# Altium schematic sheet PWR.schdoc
size 1117 x 863 mm; Symbol: Drawing-Symbol_A4; Company: 嘉立创EDA; Version: V1.0; Page Size: A4; @Project Name: OpenECG; @Update Date: 2026-05-05; @Create Date: 2026-05-05; Device: Drawing-Symbol_A4; @Board Name: #第七届立创电赛#卡片型多参数监护仪-OpenECG; @Page Name: P1; @Create Time: 15:25:49; @Page Count: 8; @Page No: 8; @Schematic Name: #第七届立创电赛#卡片型多参数监护仪-OpenECG; @Update Time: 15:25:49; @Assembly Variant: Basic; Border: 1; Title Block Position: 3; Size: A4; Width: 4400; Height: 3400; Region Start: 1; X Region Count: 6; Y Region Count: 4; Blade Width: 10
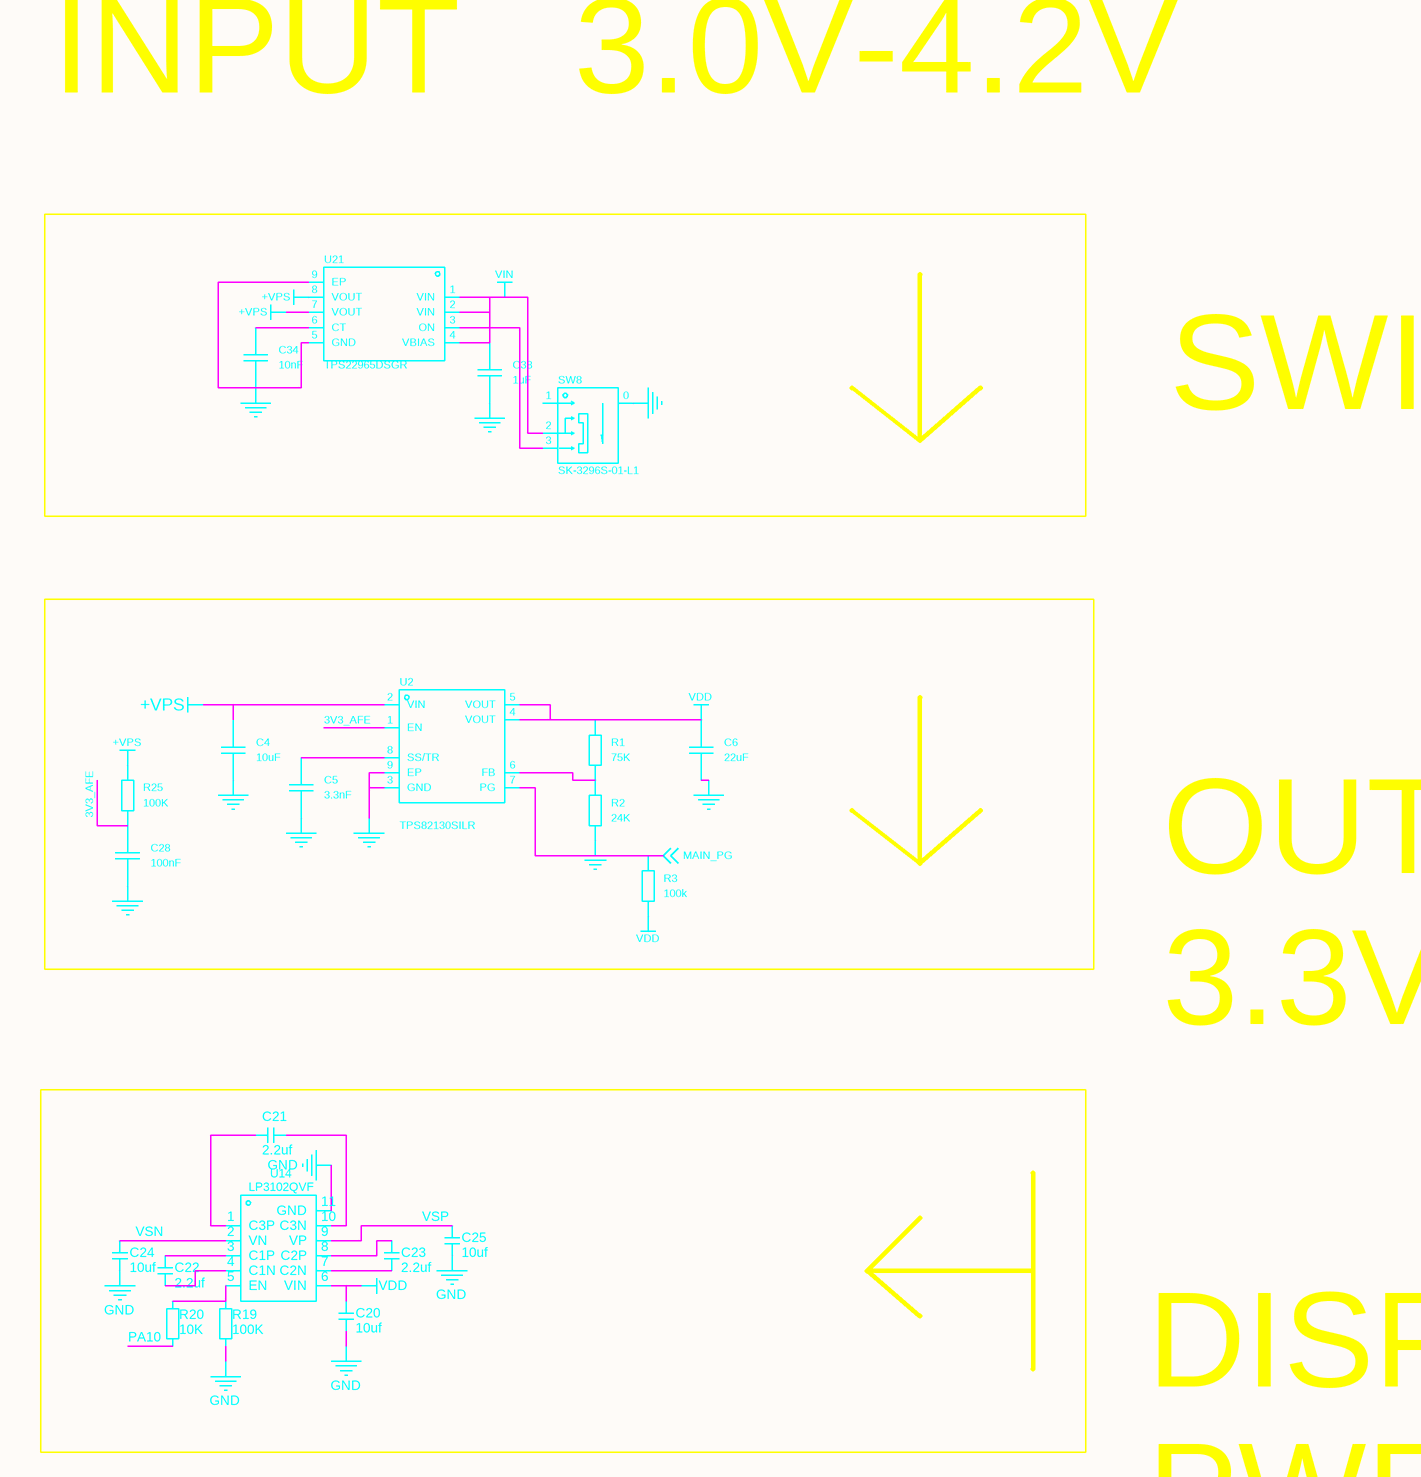
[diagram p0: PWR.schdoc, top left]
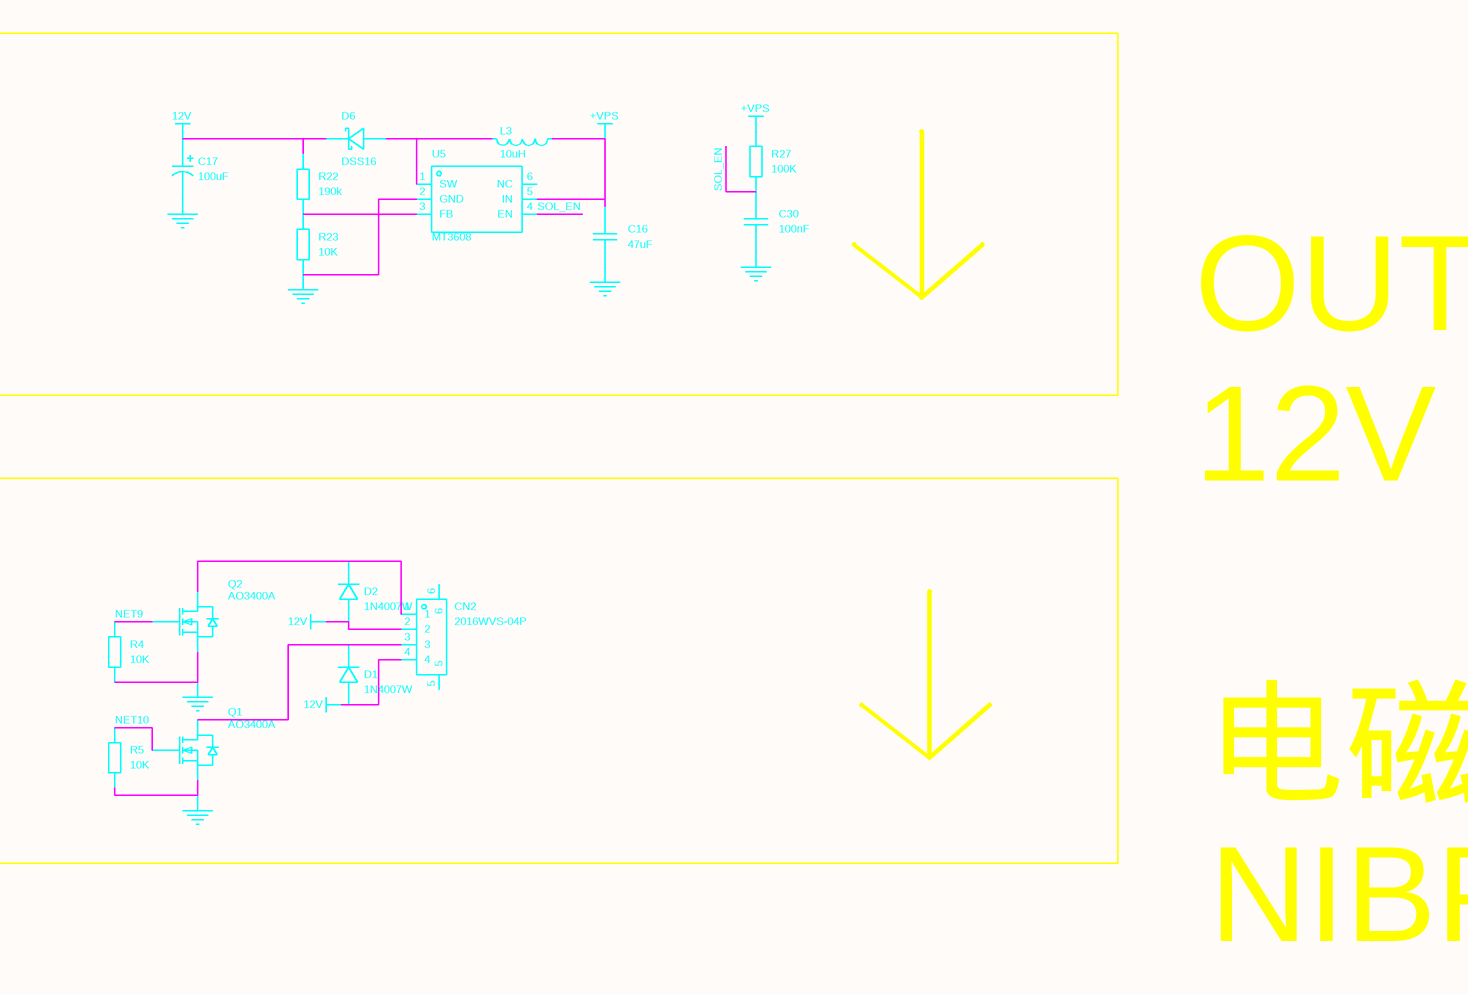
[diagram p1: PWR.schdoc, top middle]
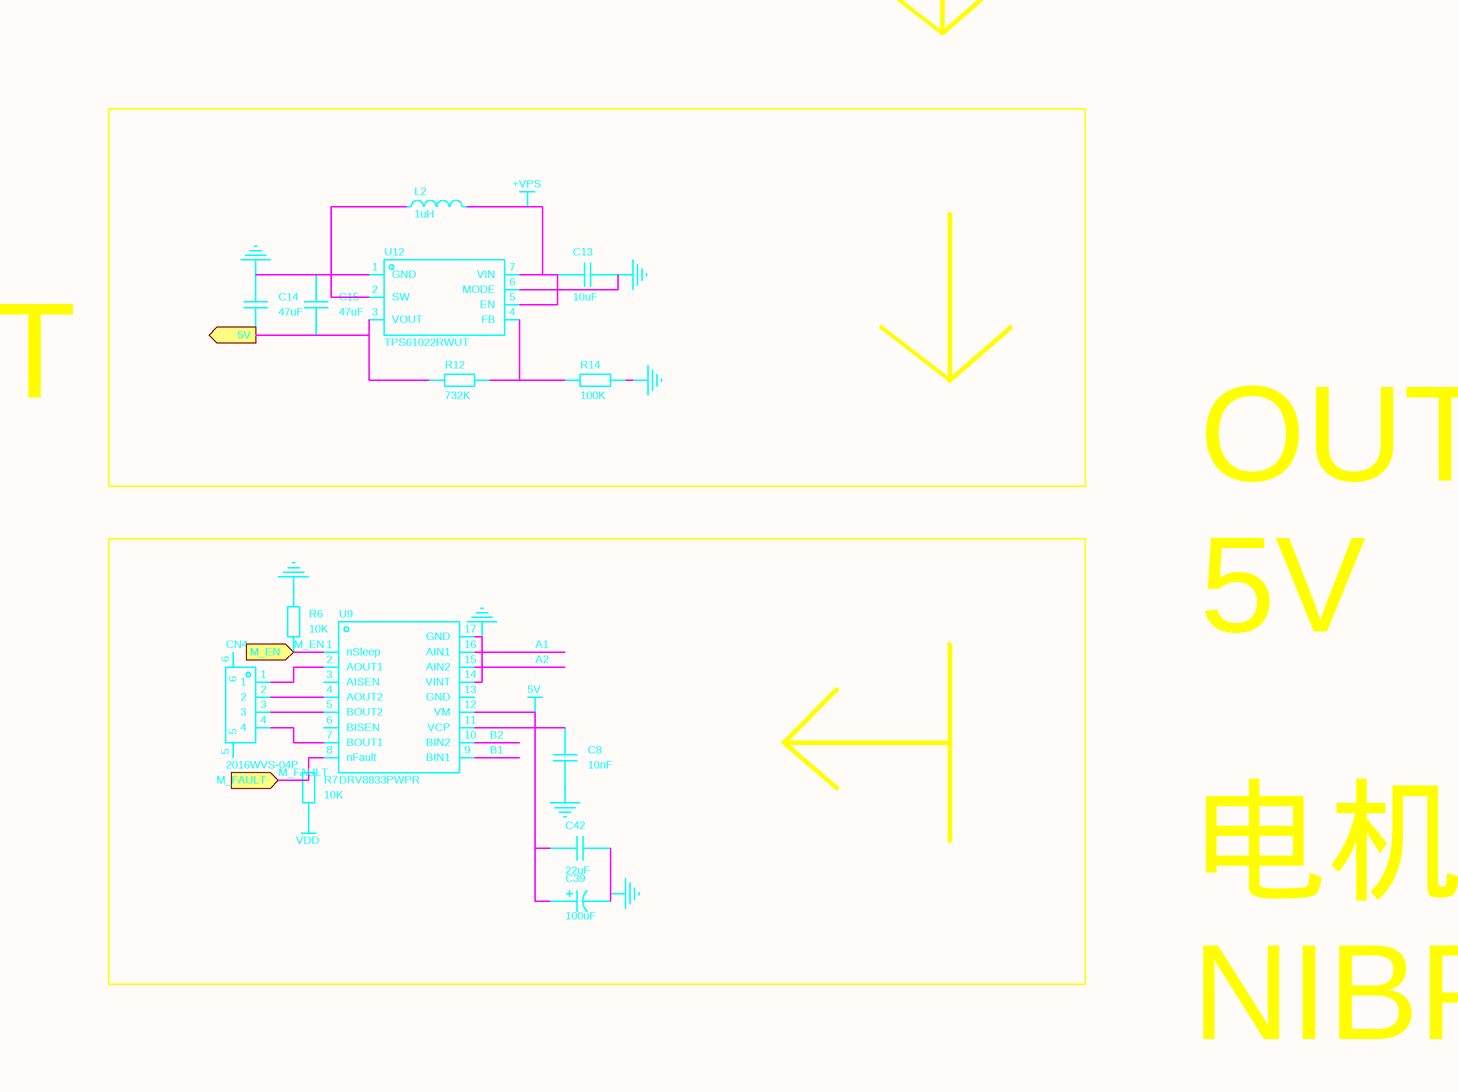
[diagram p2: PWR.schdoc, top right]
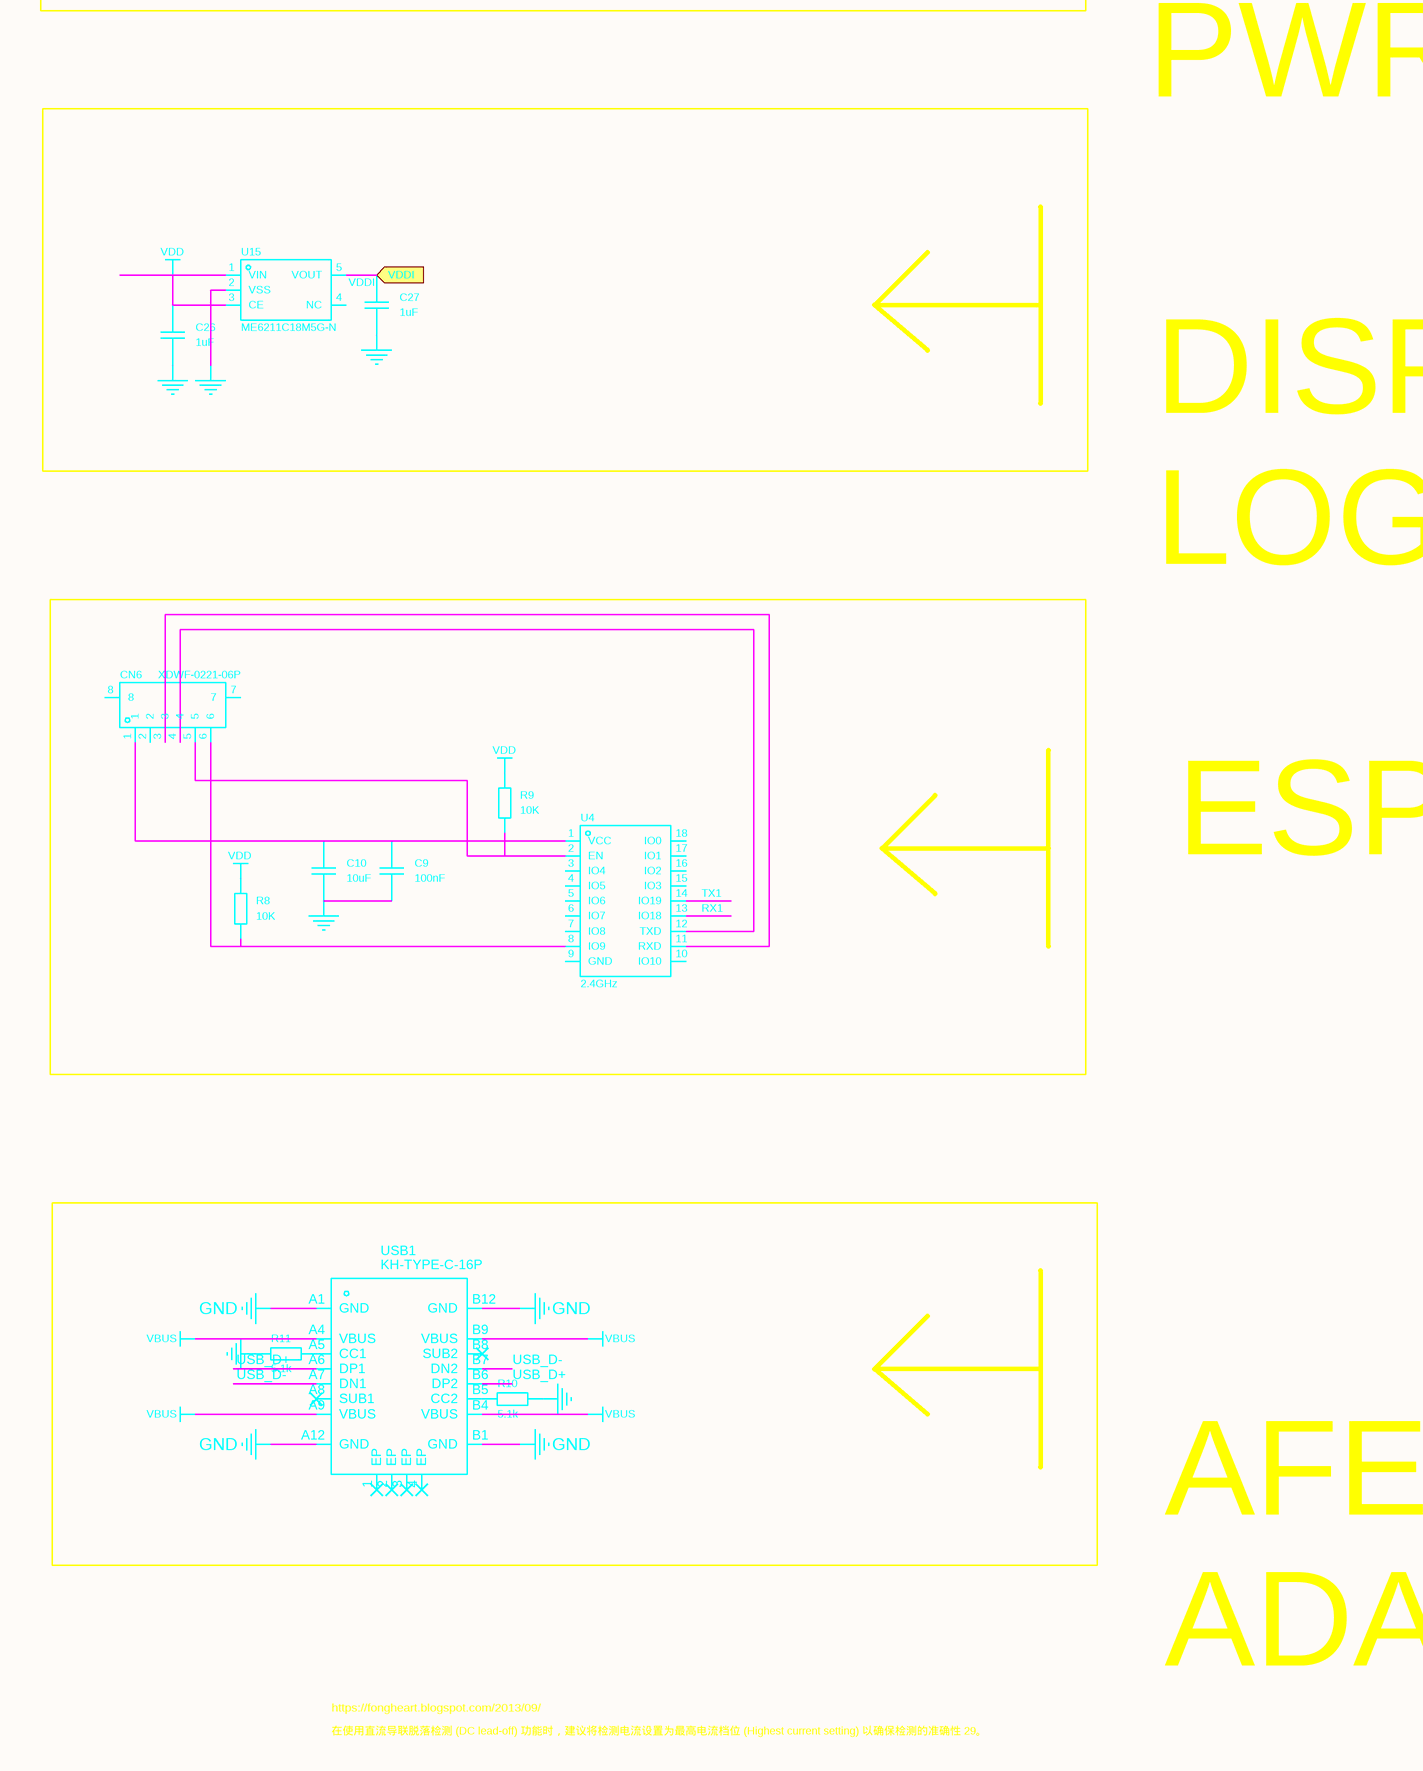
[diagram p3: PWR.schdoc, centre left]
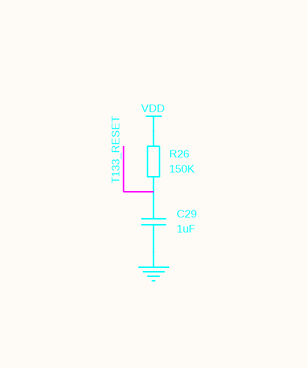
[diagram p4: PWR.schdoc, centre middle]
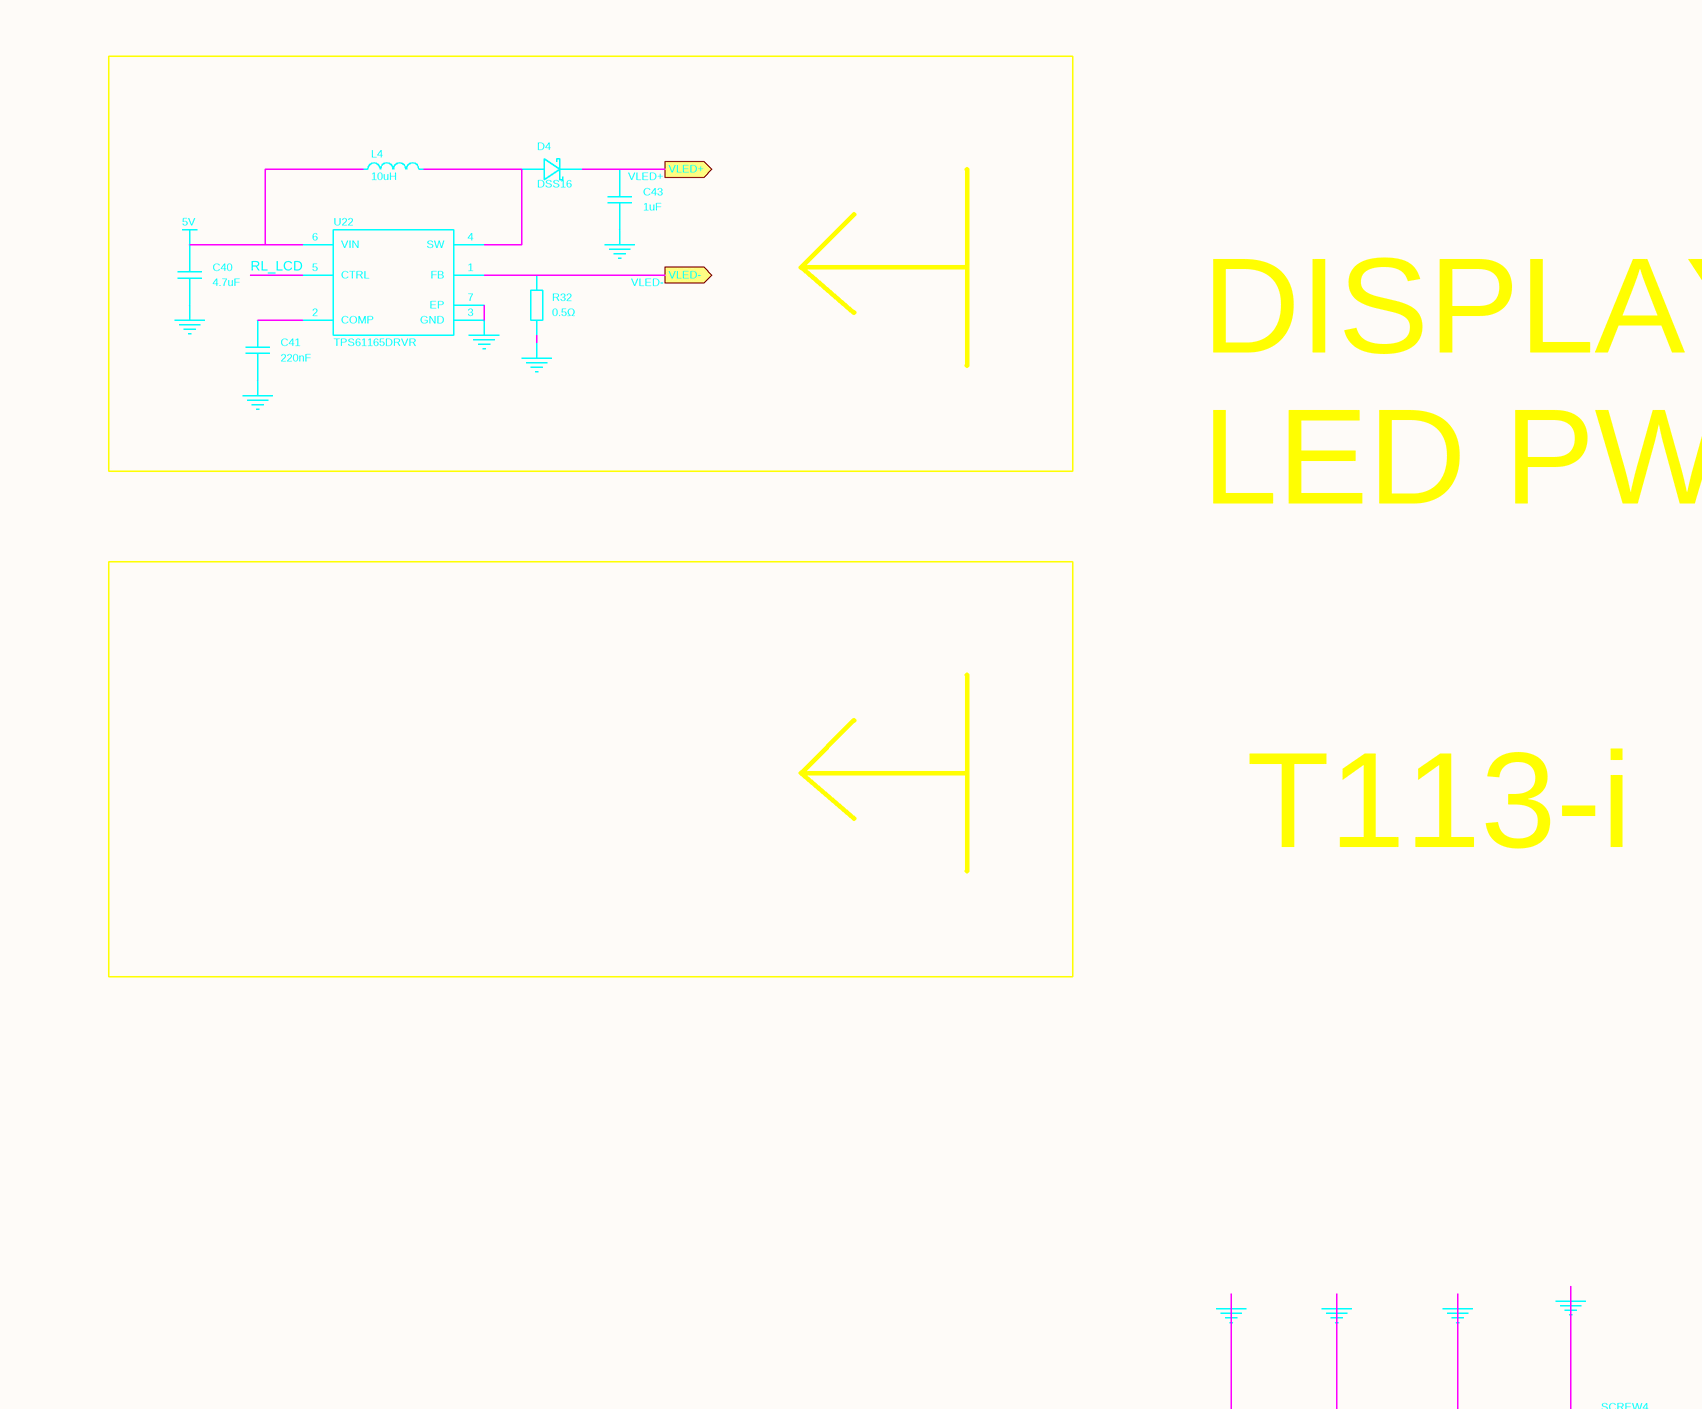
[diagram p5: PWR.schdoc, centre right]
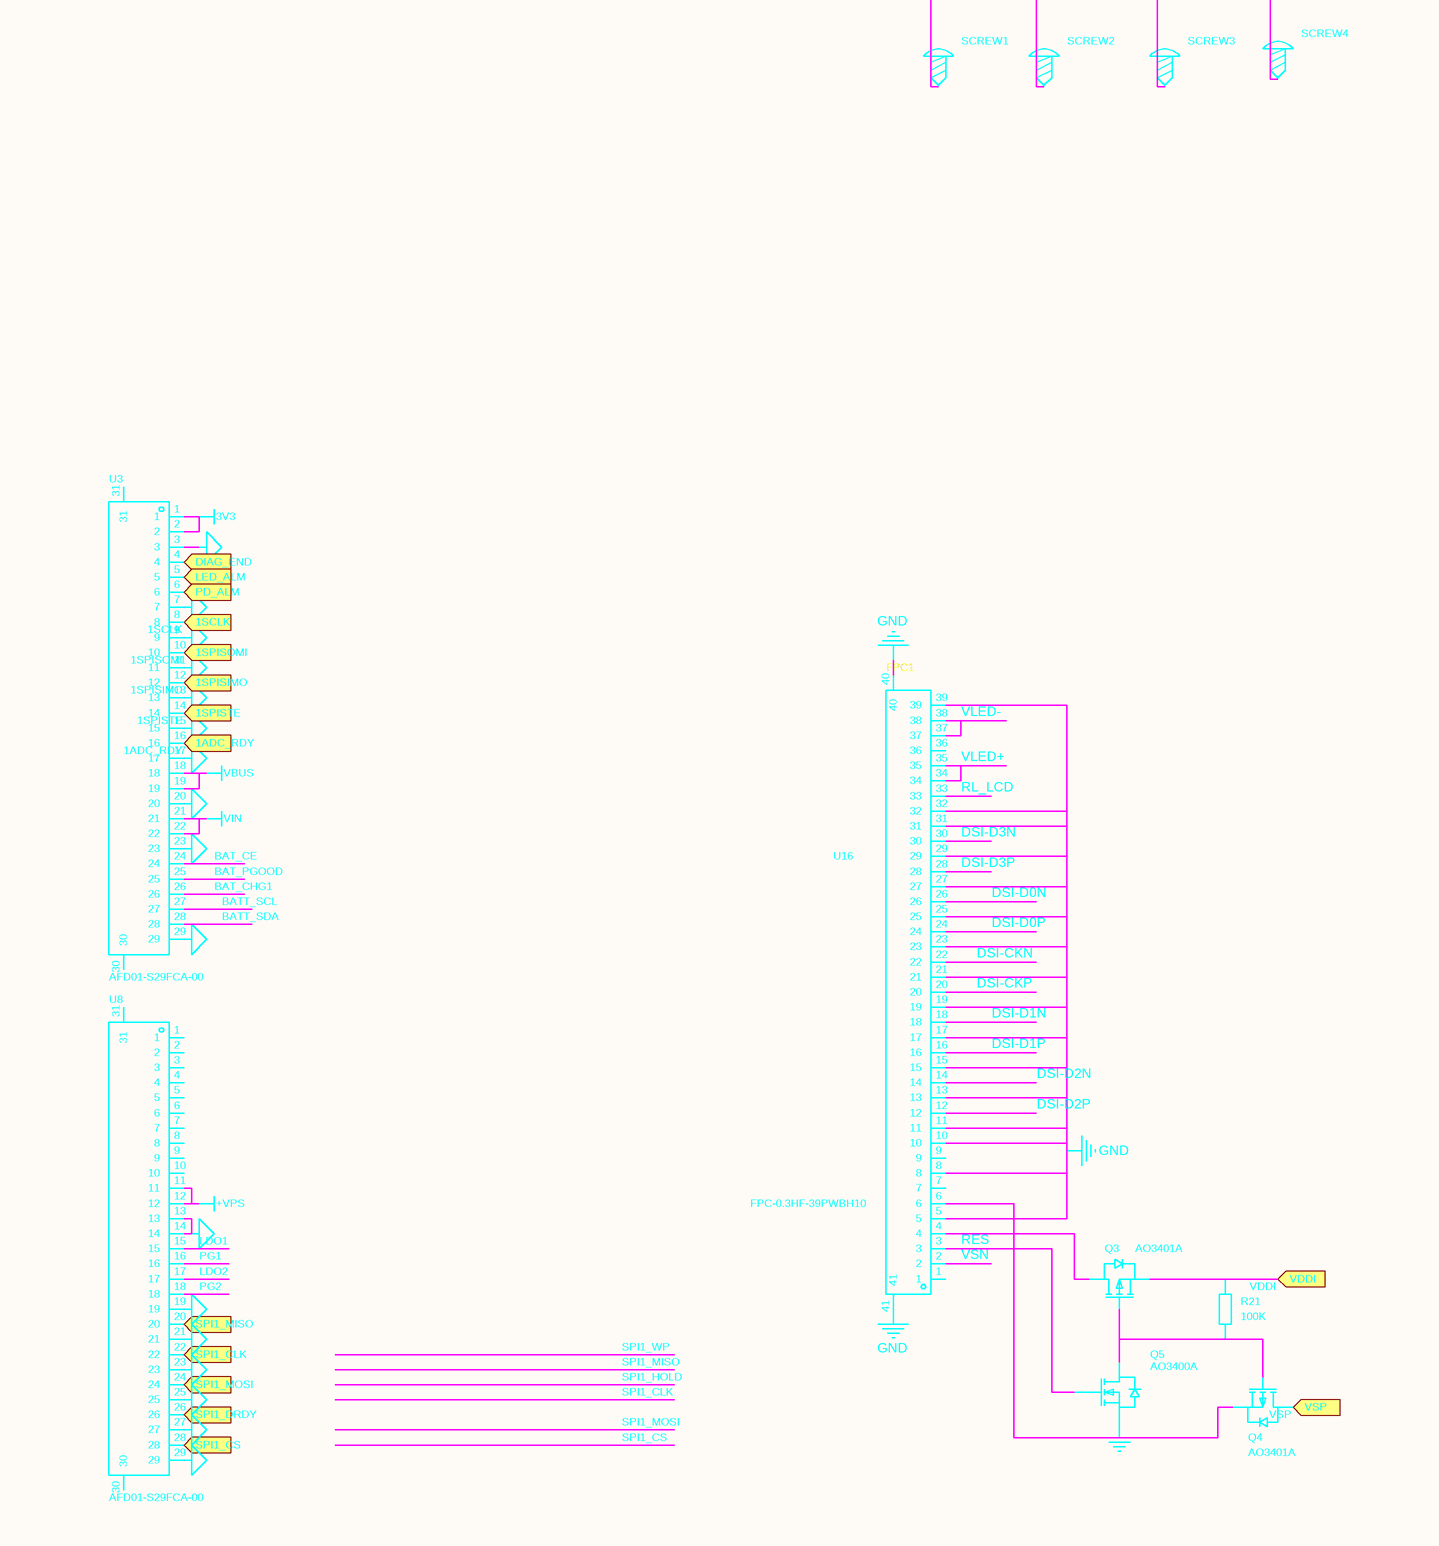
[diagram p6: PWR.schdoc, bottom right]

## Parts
C4  10uF  [C0805]
C5  3.3nF  [C0603]
C6  22uF  [C0805]
C8  10nF  [C0603]
C9  100nF  [C0603]
C10  10uF  [C0603]
C13  10uF  [C0603]
C14  47uF  [C0603]
C15  47uF  [C0603]
C16  47uF  [C0805]
C17  100uF  [CAP-SMD_BD5.0-L5.3-W5.3-LS6.0-FD-H5.7]
C20  10uf  [C0603]
C21  2.2uf  [R0603]
C22  2.2uf  [R0603]
C23  2.2uf  [R0603]
C24  10uf  [C0603]
C25  10uf  [C0603]
C26  1uF  [C0603]
C27  1uF  [C0603]
C28  100nF  [C0603]
C29  1uF  [C0603]
C30  100nF  [C0603]
C34  10nF  [C0603]
C38  1uF  [C0603]
C39  100uF  [CAP-SMD_BD5.0-L5.3-W5.3-LS6.0-FD-H5.7]
C40  4.7uF  [C0603]
C41  220nF  [C0603]
C42  22uF  [C0805]
C43  1uF  [C0603]
CN2  2016WVS-04P  [CONN-SMD_2016WVS-04P]
CN4  2016WVS-04P  [CONN-SMD_2016WVS-04P]
CN6  XDWF-0221-06P  [CONN-SMD_XDWF-0221-06P]
D1  1N4007W  [SOD-123FL_L2.7-W1.8-LS3.8-RD]
D2  1N4007W  [SOD-123FL_L2.7-W1.8-LS3.8-RD]
D4  DSS16  [SOD-123FL_L2.8-W1.8-LS3.7-R-RD]
D6  DSS16  [SOD-123FL_L2.8-W1.8-LS3.7-R-RD]
L2  1uH  [IND-SMD_L4.4-W4.2]
L3  10uH  [IND-SMD_L2.5-W2.0-VLS252012CX-150M]
L4  10uH  [IND-SMD_L2.5-W2.0_FHD252012S-6R8MT]
Q1  AO3400A  [SOT-23-3_L2.9-W1.3-P1.90-LS2.4-BR]
Q2  AO3400A  [SOT-23-3_L2.9-W1.3-P1.90-LS2.4-BR]
Q3  AO3401A  [SOT-23_L2.9-W1.3-P1.90-LS2.4-BR]
Q4  AO3401A  [SOT-23_L2.9-W1.3-P1.90-LS2.4-BR]
Q5  AO3400A  [SOT-23-3_L2.9-W1.3-P1.90-LS2.4-BR]
R1  75K  [R0603]
R2  24K  [R0603]
R3  100k  [R0603]
R4  10K  [R0603]
R5  10K  [R0603]
R6  10K  [R0603]
R7  10K  [R0603]
R8  10K  [R0603]
R9  10K  [R0603]
R10  5.1k  [R0603]
R11  5.1k  [R0603]
R12  732K  [R0603]
R14  100K  [R0603]
R19  100K  [R0603]
R20  10K  [R0603]
R21  100K  [R0603]
R22  190k  [R0603]
R23  10K  [R0603]
R25  100K  [R0603]
R26  150K  [R0603]
R27  100K  [R0603]
R32  0.5Ω  [R0603]
SCREW1  (no value)  [M3螺丝]
SCREW2  (no value)  [M3螺丝]
SCREW3  (no value)  [M3螺丝]
SCREW4  (no value)  [M3螺丝]
SW8  SK-3296S-01-L1  [SW-SMD_3P-P1.50_L2.7-W6.6]
U2  TPS82130SILR  [USIP-8_L3.0-W2.8-P0.65-TL-EP]
U3  AFD01-S29FCA-00  [FPC-SMD_29P-P0.50_JS_AFD01-S29FCA-00]
U4  2.4GHz  [WIFI-SMD_L20.0-W18.0_ESP32-C3-WROOM-02U-N4]
U5  MT3608  [SOT-23-6_L2.9-W1.6-P0.95-LS2.8-BL]
U8  AFD01-S29FCA-00  [FPC-SMD_29P-P0.50_JS_AFD01-S29FCA-00]
U9  DRV8833PWPR  [TSSOP-16_L5.0-W4.4-P0.65-LS6.4-BL-EP]
U12  TPS61022RWUT  [VQFN-7_L2.0-W2.0-P0.55-TL_RWU]
U14  LP3102QVF  [TDFN-10_L3.0-W3.0-P0.50-BL-EP]
U15  ME6211C18M5G-N  [SOT-23-5_L3.0-W1.7-P0.95-LS2.8-BR]
U16  FPC-0.3HF-39PWBH10  [LQ055T3SX02Z]
U21  TPS22965DSGR  [UDFN-8_L2.0-W2.0-P0.50-TL-EP]
U22  TPS61165DRVR  [WSON-6_L2.0-W2.0-P0.65-TL-EP]
USB1  KH-TYPE-C-16P  [USB-C-SMD_KH-TYPE-C-16P]

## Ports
1ADC_RDY (in), 1SCLK (in), 1SPISIMO (in), 1SPISOMI (in), 1SPISTE (in), 5V (out), DIAG_END (in), LED_ALM (in), M_EN (in), M_FAULT (in), PD_ALM (in), SPI1_CLK (in), SPI1_CS (in), SPI1_DRDY (in), SPI1_MISO (in), SPI1_MOSI (in), VDDI (in), VLED+ (out), VLED- (out), VSP (in)

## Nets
3V3: U3.1 U3.2
5V: C39.1 C40.2 C42.2 L4.1 U9.12(VM) U22.6(VIN)
12V: C17.1 CN2.2 CN2.4 D1.2(A) D2.2(A) D6.2(K) R22.2
+VPS: C4.1 C13.1 C16.2 L2.2 L3.1 R25.2 R27.2 U2.2(VIN) U5.5(IN) U8.11 U8.12 U12.5(EN) U12.7(VIN) U21.7(VOUT) U21.8(VOUT)
AGND: U3.3 U3.7 U3.9 U3.11 U3.13 U3.15 U3.17 U3.20 U3.23 U3.29 U8.13 U8.14 U8.19 U8.21 U8.23 U8.25 U8.27 U8.29
GND: C4.2 C5.1 C6.1 C8.1 C9.1 C10.1 C13.2 C14.2 C15.2 C16.1 C17.2 C20.1 C24.1 C25.1 C26.1 C27.1 C28.1 C29.1 C30.1 C34.1 C38.1 C39.2 C40.1 C41.1 C42.1 C43.1 Q1.2(S) Q2.2(S) Q5.2(S) R2.1 R4.1 R5.1 R6.2 R10.2 R11.1 R14.2 R19.2 R23.1 R32.1 SCREW1.1 SCREW2.1 SCREW3.1 SCREW4.1 SW8.0 U2.3(GND) U2.9(EP) U5.2(GND) U9.14(VINT) U9.17(GND) U12.1(GND) U12.6(MODE) U14.11(GND) U15.2(VSS) U16.5 U16.8 U16.10 U16.11 U16.13 U16.15 U16.17 U16.19 U16.21 U16.23 U16.25 U16.27 U16.29 U16.31 U16.32 U16.39 U16.40 U16.41 U21.5(GND) U21.9(EP) U22.3(GND) U22.7(EP) USB1.A1(GND) USB1.A12(GND) USB1.B1(GND) USB1.B12(GND)
VBUS: U3.18 U3.19 USB1.A4(VBUS) USB1.A9(VBUS) USB1.B4(VBUS) USB1.B9(VBUS)
VDD: C6.2 C20.2 C26.2 R1.2 R3.1 R7.1 R8.2 R9.2 R26.2 U2.4(VOUT) U2.5(VOUT) U14.6(VIN) U15.1(VIN) U15.3(CE)
VIN: C38.2 SW8.2 U3.21 U3.22 U21.1(VIN) U21.2(VIN) U21.4(VBIAS)
1ADC_RDY: U3.16 ; port 1ADC_RDY
1SCLK: U3.8 ; port 1SCLK
1SPISIMO: U3.12 ; port 1SPISIMO
1SPISOMI: U3.10 ; port 1SPISOMI
1SPISTE: U3.14 ; port 1SPISTE
3V3_AFE: C28.2 R25.1 U2.1(EN)
5V: C14.1 C15.1 R12.1 U12.3(VOUT) ; port 5V  [a separate net that carries the same name]
A1: U9.16(AIN1)
A2: U9.15(AIN2)
B1: U9.9(BIN1)
B2: U9.10(BIN2)
BAT_CE: U3.24
BAT_CHG1: U3.26
BAT_PGOOD: U3.25
BATT_SCL: U3.27
BATT_SDA: U3.28
DIAG_END: U3.4 ; port DIAG_END
DSI-CKN: U16.22
DSI-CKP: U16.20
DSI-D0N: U16.26
DSI-D0P: U16.24
DSI-D1N: U16.18
DSI-D1P: U16.16
DSI-D2N: U16.14
DSI-D2P: U16.12
DSI-D3N: U16.30
DSI-D3P: U16.28
LDO1: U8.15
LDO2: U8.17
LED_ALM: U3.5 ; port LED_ALM
M_EN: R6.1 U9.1(nSleep) ; port M_EN
M_FAULT: R7.2 U9.8(nFault) ; port M_FAULT
MAIN_PG: R3.2 U2.7(PG) ; off-sheet MAIN_PG
NET9: Q2.1(G) R4.2
NET10: Q1.1(G) R5.2
PA10: R20.2
PD_ALM: U3.6 ; port PD_ALM
PG1: U8.16
PG2: U8.18
RES: Q5.1(G) U16.3
RL_LCD: U16.33 U22.5(CTRL)
RX1: U4.13(IO18)
SOL_EN: C30.2 R27.1 U5.4(EN)
SPI1_CLK: U8.22 ; port SPI1_CLK
SPI1_CS: U8.28 ; port SPI1_CS
SPI1_DRDY: U8.26 ; port SPI1_DRDY
SPI1_MISO: U8.20 ; port SPI1_MISO
SPI1_MOSI: U8.24 ; port SPI1_MOSI
T133_RESET: C29.2 R26.1
TX1: U4.14(IO19)
USB_D+: USB1.A6(DP1) USB1.B6(DP2)
USB_D-: USB1.A7(DN1) USB1.B7(DN2)
VDDI: C27.2 Q3.2(S) R21.2 U15.5(VOUT) ; port VDDI
VLED+: C43.2 D4.2(K) U16.34 U16.35 ; port VLED+
VLED-: R32.2 U16.37 U16.38 U22.1(FB) ; port VLED-
VSN: C24.2 U14.2(VN) U16.2
VSP: C25.2 Q4.3(D) U14.9(VP) ; port VSP
NetC5_2: C5.2 U2.8(SS/TR)
NetC8_2: C8.2 U9.11(VCP)
NetC9_2: C9.2 C10.2 CN6.1 U4.1(VCC)
NetC21_1: C21.1 U14.10(C3N)
NetC21_2: C21.2 U14.1(C3P)
NetC22_1: C22.1 U14.3(C1P)
NetC22_2: C22.2 U14.4(C1N)
NetC23_1: C23.1 U14.8(C2P)
NetC23_2: C23.2 U14.7(C2N)
NetC34_2: C34.2 U21.6(CT)
NetC41_2: C41.2 U22.2(COMP)
NetCN2_1: CN2.1 D2.1(K) Q2.3(D)
NetCN2_3: CN2.3 D1.1(K) Q1.3(D)
NetCN4_1: CN4.1 U9.2(AOUT1)
NetCN4_2: CN4.2 U9.4(AOUT2)
NetCN4_3: CN4.3 U9.5(BOUT2)
NetCN4_4: CN4.4 U9.7(BOUT1)
NetCN6_3: CN6.3 U4.11(RXD)
NetCN6_4: CN6.4 U4.12(TXD)
NetCN6_5: CN6.5 R9.1 U4.2(EN)
NetCN6_6: CN6.6 R8.1 U4.8(IO9)
NetD4_1: D4.1(A) L4.2 U22.4(SW)
NetD6_1: D6.1(A) L3.2 U5.1(SW)
NetL2_1: L2.1 U12.2(SW)
NetQ3_1: Q3.1(G) Q4.1(G) Q5.3(D) R21.1
NetQ3_3: Q3.3(D) U16.4
NetQ4_2: Q4.2(S) U16.6
NetR1_1: R1.1 R2.2 U2.6(FB)
NetR10_1: R10.1 USB1.B5(CC2)
NetR11_2: R11.2 USB1.A5(CC1)
NetR12_2: R12.2 R14.1 U12.4(FB)
NetR19_1: R19.1 R20.1 U14.5(EN)
NetR22_1: R22.1 R23.2 U5.3(FB)
NetSW8_3: SW8.3 U21.3(ON)

Not connected (* = marked no-connect by the designer): CN2 5 6; CN4 5 6; CN6 2 7 8; SW8 1; U3 30 31; U4 3(IO4) 4(IO5) 5(IO6) 6(IO7) 7(IO8) 9(GND) 10(IO10) 15(IO3) 16(IO2) 17(IO1) 18(IO0); U5 6(NC); U8 1 2 3 4 5 6 7 8 9 10 30 31; U9 3(AISEN) 6(BISEN) 13(GND); U15 4(NC); U16 1 7 9 36; USB1 1(EP)* 2(EP)* 3(EP)* 4(EP)* A8(SUB1)* B8(SUB2)*

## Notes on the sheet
- INPUT   3.0V-4.2V
- SWITCH
- OUTPUT
  3.3V
- OUTPUT
  12V
- OUTPUT
  5V
- DISPLAY
  PWR
- 电磁阀
  NIBP
- 电机
  NIBP
- DISPLAY
  LOGIC PWR
- DISPLAY
  LED PWR
- ESP32-C3
- T113-i
- AFE4400
  ADAS1000
- https://fongheart.blogspot.com/2013/09/
- 在使用直流导联脱落检测 (DC lead-off) 功能时，建议将检测电流设置为最高电流档位 (Highest current setting) 以确保检测的准确性 29。

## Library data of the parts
C4-C6 C8-C10 C13-C16 C26-C30 C34 C38 C40 C41 C43 = CAP_0603: Symbol: Capacitance; 3D Model: ac125912035d415993ca9572d50418b1; 3D Model Transform: 62.992,31.496,0,0,0,0,0,0,0; ConvertToPcb: yes; ModelName: C0603_L1.6-W0.8-H0.8
C17 = JVJ10V100M5x5: 容值:100uF;精度:±20%;额定电压:10V;纹波电流:45mA@120Hz;; Manufacturer: JIERR(捷而瑞); 3D Model: 55d82bd915ff4bdcad2abd5b7fba61690819f05c4eef4c71ace90d822a990e87; 3D Model Transform: 236.22,208.661,0,0,0,0,0,0,0; Tolerance: ±20%; Voltage Rating: 10V; Lifetime: 2000hrs@105℃; AddInBom: yes
C20-C25 = 电容-0402: Capacitor; Value: 0.1u; Origin Footprint: CAP_0402; Origin 3D Model Title: User Library-0603 SMD Capacitor; AddInBom: yes
C39 = JVJ10V100M5x5: 容值:100uF;精度:±20%;额定电压:10V;纹波电流:45mA@120Hz;; Manufacturer: JIERR(捷而瑞); AddInBom: yes; ModelId: 55d82bd915ff4bdcad2abd5b7fba61690819f05c4eef4c71ace90d822a990e87; ModelTransform: 236.22,208.661,0,0,0,0,0,0,0; Tolerance: ±20%; Voltage Rating: 10V; Lifetime: 2000hrs@105℃
C42 = C2012X5R1V226MT000E: 容值:22uF;精度:±20%;额定电压:35V;温度系数:X5R;; Manufacturer: TDK; AddInBom: yes; ModelId: 1ba041120af144c991958decab20d2410819f05c4eef4c71ace90d822a990e87; ModelName: C0805_L2.0-W1.3-H1.3; ModelTransform: 78.74,51.181,0,0,0,0,0,0.0005,0; Tolerance: ±20%; Voltage Rating: 35V; Temperature Coefficient: X5R
CN2 CN4 = 2016WVS-04P: 插针结构:1x4P;间距:2mm;安装方式:立贴;参考系列:PH;总PIN数:4P;排数:1;每排PIN数:4;触头材质:黄铜;触头镀层:锡;; Manufacturer: HanElectricity(瀚源); Pins Structure: 1x4P; Pitch: 2mm; Reference Series: PH; Number of PINs Per Row: 4; Plastic Material: LCP; Flame Retardant Rating: UL94V-0; Z-Height of the Board: 6.2mm; Y-Width of Bottom Edge on Board: 5.4mm; AddInBom: yes
CN6 = XDWF-0221-06P: 插针结构:1x6P;间距:2mm;安装方式:立贴;总PIN数:6P;排数:1;每排PIN数:6;额定电流:3A;触头材质:铜;触头镀层:锡;工作温度:-40℃~+85℃;; Manufacturer: LX(连欣科技); AddInBom: yes; ModelId: 3330ab840f6a417aaed60c53b1a588890819f05c4eef4c71ace90d822a990e87; ModelTransform: 627.952,293.3065,0,0,0,0,0,-40.905,0; Pins Structure: 1x6P; Pitch: 2mm; Number of PINs Per Row: 6; Current Rating: 3A; Voltage Rating: 100V; Plastic Material: LCP; Z-Height of the Board: 7.4mm; Y-Width of Bottom Edge on Board: 7.45mm
D1 D2 = 1N4007W_C18199088: 二极管配置:独立式;正向压降(Vf):1V@1A;直流反向耐压(Vr):1kV;整流电流:1A;; Manufacturer: R+O(宏嘉诚); 3D Model: 86f9151e155e4fe2af0c4f2e0a80302e0819f05c4eef4c71ace90d822a990e87; 3D Model Transform: 141.732,70.866,0,180,0,0,0,0,0; Diode Configuration: 独立式; Voltage - Forward(Vf@If): 1V@1A; Voltage - DC Reverse(Vr): 1kV; Current - Rectified: 1A; Reverse Leakage Current (Ir): 2uA@1000V; Non-Repetitive Peak Forward Surge Current: 30A; Operating Junction Temperature Range: -55℃~+150℃; AddInBom: yes; ModelName: SOD-123FL_L2.8-W1.8-H1.1-LS3.6
D4 = DSS16_C2923924: 二极管配置:独立式;正向压降(Vf):700mV@1A;直流反向耐压(Vr):60V;整流电流:1A;; Manufacturer: CJ(江苏长电/长晶); AddInBom: yes; ModelId: 8393683a03e6444f97e03ed1558f3a520819f05c4eef4c71ace90d822a990e87; ModelTransform: 143.701,70.3249,0,0,0,0,0,0,0; Diode Configuration: 独立式; Voltage - DC Reverse(Vr): 60V; Current - Rectified: 1A; Reverse Leakage Current (Ir): 500uA@60V; Operating Junction Temperature Range: -55℃~+150℃; Non-Repetitive Peak Forward Surge Current: 30A
D6 = DSS16_C2923924: 二极管配置:独立式;正向压降(Vf):700mV@1A;直流反向耐压(Vr):60V;整流电流:1A;; Manufacturer: CJ(江苏长电/长晶); 3D Model: 8393683a03e6444f97e03ed1558f3a520819f05c4eef4c71ace90d822a990e87; 3D Model Transform: 143.701,70.3249,0,0,0,0,0,0,0; Diode Configuration: 独立式; Voltage - DC Reverse(Vr): 60V; Current - Rectified: 1A; Reverse Leakage Current (Ir): 500uA@60V; Operating Junction Temperature Range: -55℃~+150℃; Non-Repetitive Peak Forward Surge Current: 30A; AddInBom: yes
L2 = FXL0420-1R0-M: 电感值:1uH;精度:±20%;额定电流:6A;饱和电流(Isat):7A;类型:一体成型电感;; Manufacturer: cjiang(长江微电); AddInBom: yes; ModelId: e9b3d3f4fa134185b54d517730715f160819f05c4eef4c71ace90d822a990e87; ModelName: IND-SMD_L4.2-W4.4-H2.0; ModelTransform: 173.228,165.354,0,0,0,0,0,0,0; Tolerance: ±20%; Rated Current: 6A; Saturation Current (Isat): 7A; DC Resistance (DCR): 27mΩ; Type: 一体成型电感
L3 = YNR2512-100M: 电感值:10uH;精度:±20%;额定电流:620mA;类型:磁胶屏蔽电感;; Manufacturer: YJYCOIN(益嘉源); 3D Model: e143e04106934774881cec608355723f0819f05c4eef4c71ace90d822a990e87; 3D Model Transform: 98.504,78.819,0,0,0,0,-0.004,-0.003,0; Tolerance: ±20%; Current Rating: 620mA; DC Resistance(DCR): 531mΩ; Type: 磁胶屏蔽电感; AddInBom: yes
L4 = FHD252012S-100MT: 电感值:10uH;精度:±20%;额定电流:1A;饱和电流(Isat):1.35A;类型:绕线电感;; Manufacturer: cjiang(长江微电); AddInBom: yes; ModelId: 205a9014ebaa4c78b537aa85d0a12f770819f05c4eef4c71ace90d822a990e87; ModelTransform: 78.74,99.2124,0,90,0,0,0,0,0; Tolerance: ±20%; Current Rating: 1A; Current - Saturation(Isat): 1.35A; DC Resistance(DCR): 435mΩ; Type: 绕线电感
Q1 Q2 Q5 = AO3400A_C20917: 数量:-;漏源电压(Vdss):30V;连续漏极电流(Id):-;导通电阻(RDS(on)):48mΩ@2.5V;耗散功率(Pd):-;阈值电压(Vgs(th)):1.45V@250uA;; Manufacturer: AOS; 3D Model: c62791f0466c4ae2a892c056b845b0ca0819f05c4eef4c71ace90d822a990e87; 3D Model Transform: 98.425,114.173,0,180,0,0,0.0005,-0.0005,0; Drain to Source Voltage: 30V; Gate Charge(Qg): 7nC@10V; Input Capacitance(Ciss): 630pF@15V; Type: N沟道; AddInBom: yes; ModelName: SOT-23-3P_L2.9-W1.3-H1.0-LS2.4-P0.95
Q3 Q4 = AO3401A_C347476: 数量:1个P沟道;漏源电压(Vdss):30V;连续漏极电流(Id):4.2A;导通电阻(RDS(on)):50mΩ@10V;耗散功率(Pd):1.4W;阈值电压(Vgs(th)):1.3V@250uA;; Manufacturer: UMW(友台半导体); 3D Model: c62791f0466c4ae2a892c056b845b0ca0819f05c4eef4c71ace90d822a990e87; 3D Model Transform: 98.64468,114.173,0,180,0,0,0.001,-0.002,0; Number: 1个P沟道; Drain to Source Voltage: 30V; Current - Continuous Drain(Id): 4.2A; Pd - Power Dissipation: 1.4W; Gate Charge(Qg): 9.4nC@4.5V; Input Capacitance(Ciss): 954pF; Reverse Transfer Capacitance (Crss@Vds): 77pF; Type: P沟道; Output Capacitance(Coss): 115pF; AddInBom: yes; ModelName: SOT-23-3P_L2.9-W1.3-H1.0-LS2.4-P0.95
R1-R12 R14 R21-R23 R25-R27 R32 = Res_0603: Symbol: 电阻; 3D Model: fc143cca1e79419f9cd78b61e9279f08; 3D Model Transform: 31.8897,63.7794,0,90,0,0,0,0,0; ConvertToPcb: yes
R19 R20 = 电阻-0402: Resistor; Value: 22R; Origin Footprint: RES_0402; Origin 3D Model Title: SW3dPS-0603 SMD Resistor; AddInBom: yes
SCREW1-SCREW4 = M3螺丝: Symbol: 螺丝孔; ConvertToPcb: yes
SW8 = SK-3296S-01-L1: 电路结构:单刀双掷;安装方式:卧贴;开关颜色:黑色;额定电流:50mA;额定电压:12V;工作寿命:1万次;; Manufacturer: XKB Connection(中国星坤); AddInBom: yes; ModelId: fac986d38b354d44b3f03575504711090819f05c4eef4c71ace90d822a990e87; ModelName: SW-SMD_3P-L6.6-W2.7-LS7.8-P1.50; ModelTransform: 307.086,204.724,0,180,0,0,0,-28.898,-19.685; Circuit: 单刀双掷; Actuator Style: 矩形柱状; Switch Height: 1.35mm; Actuator Color: 黑色; Current Rating: 50mA; Voltage Rating: 12V; Life: 1万次
U2 = TPS82130SILR: TPS82130 TPS82130 具有集成电感的 3A 17V 降压转换器; Manufacturer: TI(德州仪器); AddInBom: yes; ModelId: 8242d4cc836b419a87062e2788069e290819f05c4eef4c71ace90d822a990e87; ModelTransform: 110.236,118.11,0,180,0,0,0,0,0; Function: 降压型; Number of Outputs: 1; Voltage - Supply: 3V~17V; Output Voltage Accuracy: ±1.5%; Output Voltage: 900mV~6V; Supply Current (Iq): 20uA; Switching Frequency: 2MHz
U3 = AFD01-S29FCA-00: 锁定特性:翻盖式;触点类型:下接;触点数量:29P;间距:0.5mm;安装方式:卧贴;; Manufacturer: JS(钜硕电子); 3D Model: d3d70d81697947e89ddc2db5d0f11f510819f05c4eef4c71ace90d822a990e87; 3D Model Transform: 783.463,240.157,0,0,0,0,-0.002,71.104,0; Locking Feature: 翻盖式; Number of Contacts: 29P; Pitch: 0.5mm; AddInBom: yes
U4 = ESPC3-20-N4: 核心芯片:-;频率:2.4GHz;天线形式:PCB;发射功率:18dBm;接收灵敏度:-98dBm;; Manufacturer: DOIT(四博智联); AddInBom: yes; ModelId: 77e27fd9f9e343e7b34d3721352b971a0819f05c4eef4c71ace90d822a990e87; ModelTransform: 708.66,787.4,0,0,0,0,0,120.984,0; Wireless Standard: WIFI4；BLE5.0; Interface Type: UART; Antenna Type: PCB; Output Power: 18dBm; Voltage - Supply: 3.3V; Receive  Current: 60mA; Send  Current: 385mA; Sensitivity: -98dBm
U5 = MT3608: 功能类型:升压型;输出类型:可调;工作电压:2V~24V;输出电压:-;输出电流:2A;; Manufacturer: 西安航天民芯; 3D Model: 18da8f6c14a34920b3e136b5c401a1190819f05c4eef4c71ace90d822a990e87; 3D Model Transform: 110.236,113.364,0,90,0,0,0.0005,0.0005,0; Function: 升压型; Output Type: 可调; Voltage - Supply: 2V~24V; Output Current: 2A; Frequency - Switching: 1.2MHz; Synchronous Rectifier: 否; Number of Outputs: 1; Topology: 升压式; Quiescent Current: 100uA；1.6mA; Switch tube (built-in/external): 内置; AddInBom: yes; ModelName: SOT-23-6_L2.9-W1.6-H1.5-LS2.8-P0.95
U8 = AFD01-S29FCA-00: 锁定特性:翻盖式;触点类型:下接;触点数量:29P;间距:0.5mm;安装方式:卧贴;; Manufacturer: JS(钜硕电子); AddInBom: yes; ModelId: d3d70d81697947e89ddc2db5d0f11f510819f05c4eef4c71ace90d822a990e87; ModelTransform: 783.463,240.157,0,0,0,0,-0.002,71.104,0; Locking Feature: 翻盖式; Number of Contacts: 29P; Pitch: 0.5mm
U9 = DRV8833PWPR: DRV8833 具有电流调节功能的 10.8V、2A、双通道 H 桥电机驱动器; Manufacturer: TI(德州仪器); 3D Model: e184b9ae7def452b81228c95a013214c0819f05c4eef4c71ace90d822a990e87; 3D Model Transform: 252.188,196.85,0,90,0,0,0,0,0; Motor Drive Voltage(Vm): 2.7V~10.8V; Output Current: 1.5A; Number of H-bridges: 2; Drive Type: 双极驱动; RDS(on): 360mΩ; AddInBom: yes; ModelName: TSSOP-16_L5.0-W4.4-H1.0-LS6.4-P0.65
U12 = TPS61022RWUT: 功能类型:升压型;工作电压:500mV~5.5V;输出电压:2.2V~5.5V;输出电流:8A;输出类型:可调;; Manufacturer: TI(德州仪器); AddInBom: yes; ModelId: a0001088333a4c7882d5799561416a3e0819f05c4eef4c71ace90d822a990e87; ModelTransform: 79.527,78.74,0,0,0,0,-6.496,0,0; Function: 升压型; Output Current: 8A; Frequency - Switching: 600kHz~1MHz; Synchronous Rectifier: 是; Number of Outputs: 1; Topology: 升压式; Quiescent Current: 3uA; Switch tube (built-in/external): 内置; Output Type: 可调
U14 = LP3102QVF: BOM_Manufacturer: LOWPOWER; Contributor: LCSC; SMT Type: Extend; AddInBom: yes
U15 = ME6211C18M5G-N: 输出类型:固定;工作电压:6V;输出电压:1.8V;输出电流:300mA;电源纹波抑制比(PSRR):70dB@(1kHz);输出极性:正极;; Manufacturer: MICRONE(南京微盟); 3D Model: 0a2a1b8f50944f73965918ad6e5fe1670819f05c4eef4c71ace90d822a990e87; 3D Model Transform: 114.173,109.636,0,180,0,0,0,0,0; Output Type: 固定; Voltage - Supply: 6V; Output Voltage: 1.8V; Output Current: 300mA; Voltage Dropout: 200mV@(100mA)；400mV@(200mA); standby current: 30uA; Noise: 50uVrms; Output Configuration: 正极; Number of Outputs: 1; AddInBom: yes; ModelName: SOT-23-5_L2.9-W1.6-H1.1-LS2.8-P0.95
U16 = FPC-0.3HF-39PWBH10: 锁定特性:翻盖式;触点类型:双侧触点/上下接;触点数量:39P;间距:0.3mm;安装方式:卧贴;工作温度:-55℃~+85℃;; Manufacturer: XUNPU(讯普); Locking Feature: 翻盖式; Number of Contacts: 39P; Pitch: 0.3mm; Rated Voltage (Max): 30V; Current Rating (Max): 200mA; AddInBom: yes
U21 = TPS22965DSGR: 类型:负载开关;通道数:1;输入控制逻辑:高电平有效;最大连续电流:6A;工作电压:800mV~5.7V;导通电阻:16mΩ;; Manufacturer: TI(德州仪器); AddInBom: yes; ModelId: 946e25d6e4b040a1926ac3aab630211e0819f05c4eef4c71ace90d822a990e87; ModelName: UDFN-8_L2.0-W2.0-H0.8-P0.50; ModelTransform: 78.74,77.96,0,0,0,0,0,0,0; Number of Channels: 1; Control Input Logic: 高电平有效; Maximum Continuous Current: 6A; RDS(on): 16mΩ
U22 = TPS61165DRVR: 类型:DC-DC;工作电压(DC):3V~18V;开关频率:1.2MHz;通道数:1;输出电压:3V~38V;输出电流:1.2A;调光:PWM;拓扑结构:升压;; Manufacturer: TI(德州仪器); AddInBom: yes; ModelId: 521c6d8f59ad4736925338f4a59f8ef40819f05c4eef4c71ace90d822a990e87; ModelName: WSON-6_L2.0-W2.0-H0.8-P0.65; ModelTransform: 79.527,78.74,0,0,0,0,0,0,0; Voltage - Input(DC): 3V~18V; Frequency - Switching: 1.2MHz; Number of Channels: 1; Output Voltage: 3V~38V; Output Current: 1.2A; Dimming: PWM; Topology: 升压; Switch Tube (Built-In/External): 内置; Constant Current Accuracy: 2%
USB1 = KH-TYPE-C-16P: Manufacturer: Shenzhen Kinghelm Elec; Add into BOM: yes; Origin 3D Model Title: USB-C_SMD-TYPE-C-31-M-12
